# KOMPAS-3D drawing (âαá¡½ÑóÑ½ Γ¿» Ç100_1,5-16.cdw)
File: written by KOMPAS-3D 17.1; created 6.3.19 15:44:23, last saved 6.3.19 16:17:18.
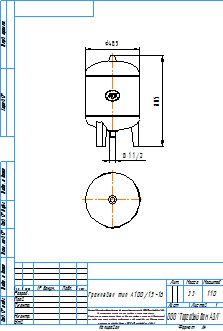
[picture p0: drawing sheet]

Sheet 1: A4, portrait

Title block, sheet 1: name: Гранлевел тип А100/1,5-16; material: Сталь 10  ГОСТ 1050-88; mass: 33; sheets: 1; sheet format: A4; stored path: C:\Users\kka\KOMPAS_Work\!Trash\ГРАНЛЕВЕЛ тип А Расширительный бак\KOMPAS 2D\Гранлевел тип А100_1,5-16.cdw

Views: Вид 1, Проекционный вид 2
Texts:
  kka
  adl
  Рама для чертежей
  Лит-Масса-Масштаб
  Материал-Предприятие
  Масштаб
  Изм.
  Лист
  № докум.
  Подп.
  Дата
  Лит.
  Разраб.
  Пров.
  Т.контр.
  Листов
  Внимание! Данный продукт является объектом авторского права ООО «Торговый Дом АДЛ».
  Запрещается изменение, копирование, распространение
  (в том числе путем копирования на другие сайты и ресурсы в Интернете)
  или любое иное использование информации и объектов без предварительного
  согласия правообладателя (ООО «Торговый Дом АДЛ»).
  Н.контр.
  Утв.
  ООО "Торговый дом АДЛ"
  Изменение
  Номер документа
  Подпись
  Обозначение документа
  Наименование изделия
  Масса изделия по ГОСТ 2.109-73
  Порядковый номер листа
  Общее количество листов в документе
  Характер работы, выполненной лицом, подписавшим документ
  Наименование или индекс предприятия, выпускающего документ
  Инв. № подл.
  Подп. и дата
  Взам. инв. №
  Инв. № дубл.
  Инвентарный номер подлинника по ГОСТ 2.501-68
  Подпись принявшего подлинник в отдел технической документации
  Инвентарный номер подлинника, взамен которого выпущен данный подлинник
  Инвентарный номер дубликата по ГОСТ 2.502-68
  Подпись принявшего дубликат в отдел технической документации
  Справ. №
  Перв. примен.
  Обозначение документа, взамен или на основании которого выпущен данный документ
  Обозначение документа, в котором впервые записан данный документ
  Подпись лица, копировавшего чертеж
  Обозначение формата листа
  !Рама для чертежа
Dimensions and other numbers on the sheet: 805; 485; 1 1/2; 1:10; 1; 33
